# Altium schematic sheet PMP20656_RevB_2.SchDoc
size 431 x 279 mm; Date: Not shown in title block; ApprovedBy: Not shown in title block; CheckedBy: Not shown in title block; Author: Not shown in title block; CompanyName: Not shown in title block; Engineer: Not shown in title block; Organization: Not shown in title block; Address1: Not shown in title block; Address2: Not shown in title block; Address3: Not shown in title block; Address4: Not shown in title block; DocumentNumber: 2; Revision: Use project parameter SCH_Rev; SheetNumber: 2; SheetTotal: 2; PageSetup: Record=PageOptions¦CenterHorizontal=True¦CenterVertical=True¦PrintScale=1.00¦XCorrection=1.00¦YCorrection=1.00¦PrintKind=0¦BorderSize=5000000¦LeftOffset=0¦BottomOffset=0¦Orientation=2¦PaperLength=1000¦PaperWidth=1000¦Scale=100¦PaperSource=15¦PrintQuality=600¦MediaType=1¦DitherType=10¦PaperKind=Letter¦PrintScaleMode=1
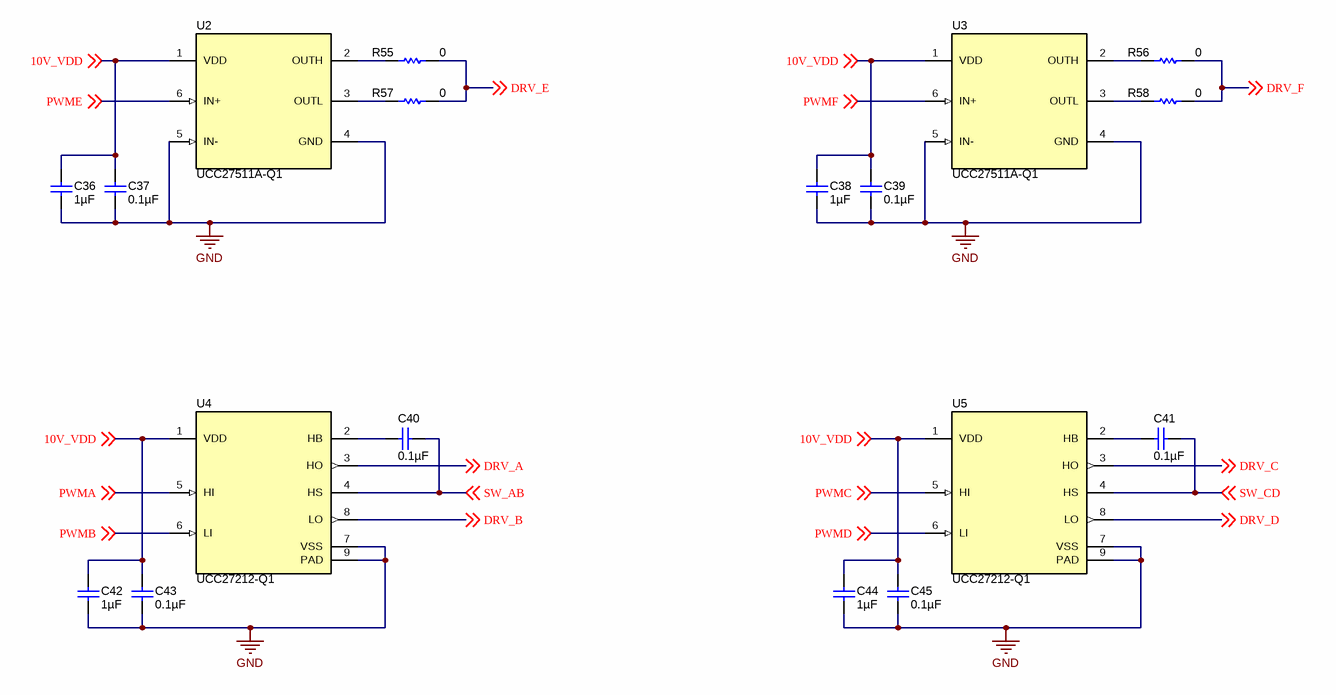
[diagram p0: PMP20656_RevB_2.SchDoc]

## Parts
C36  ValueDisplayed: 1µF  [0603L]  (hidden comment: GRM188R71E105KA12D)
C37  ValueDisplayed: 0.1µF  [0603L]  (hidden comment: GRM188R71H104KA93D)
C38  ValueDisplayed: 1µF  [0603L]  (hidden comment: GRM188R71E105KA12D)
C39  ValueDisplayed: 0.1µF  [0603L]  (hidden comment: GRM188R71H104KA93D)
C40  ValueDisplayed: 0.1µF  [0603L]  (hidden comment: GRM188R71H104KA93D)
C41  ValueDisplayed: 0.1µF  [0603L]  (hidden comment: GRM188R71H104KA93D)
C42  ValueDisplayed: 1µF  [0603L]  (hidden comment: GRM188R71E105KA12D)
C43  ValueDisplayed: 0.1µF  [0603L]  (hidden comment: GRM188R71H104KA93D)
C44  ValueDisplayed: 1µF  [0603L]  (hidden comment: GRM188R71E105KA12D)
C45  ValueDisplayed: 0.1µF  [0603L]  (hidden comment: GRM188R71H104KA93D)
R55  ValueDisplayed: 0  [0603L]  (hidden comment: CRCW06030000Z0EA)
R56  ValueDisplayed: 0  [0603L]  (hidden comment: CRCW06030000Z0EA)
R57  ValueDisplayed: 0  [0603L]  (hidden comment: CRCW06030000Z0EA)
R58  ValueDisplayed: 0  [0603L]  (hidden comment: CRCW06030000Z0EA)
U2  UCC27511A-Q1  [DBV0006A_N]
U3  UCC27511A-Q1  [DBV0006A_N]
U4  UCC27212-Q1  [DDA0008E_N]
U5  UCC27212-Q1  [DDA0008E_N]

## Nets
GND: C36.2 C37.2 C38.2 C39.2 C42.2 C43.2 C44.2 C45.2 U2.4(GND) U2.5(IN-) U3.4(GND) U3.5(IN-) U4.7(VSS) U4.9(PAD) U5.7(VSS) U5.9(PAD)
10V_VDD: C36.1 C37.1 C38.1 C39.1 C42.1 C43.1 C44.1 C45.1 U2.1(VDD) U3.1(VDD) U4.1(VDD) U5.1(VDD) ; off-sheet 10V_VDD
DRV_A: U4.3(HO) ; off-sheet DRV_A
DRV_B: U4.8(LO) ; off-sheet DRV_B
DRV_C: U5.3(HO) ; off-sheet DRV_C
DRV_D: U5.8(LO) ; off-sheet DRV_D
DRV_E: R55.1 R57.1 ; off-sheet DRV_E
DRV_F: R56.1 R58.1 ; off-sheet DRV_F
PWMA: U4.5(HI) ; off-sheet PWMA
PWMB: U4.6(LI) ; off-sheet PWMB
PWMC: U5.5(HI) ; off-sheet PWMC
PWMD: U5.6(LI) ; off-sheet PWMD
PWME: U2.6(IN+) ; off-sheet PWME
PWMF: U3.6(IN+) ; off-sheet PWMF
SW_AB: C40.2 U4.4(HS) ; off-sheet SW_AB
SW_CD: C41.2 U5.4(HS) ; off-sheet SW_CD
NetC40_1: C40.1 U4.2(HB)
NetC41_1: C41.1 U5.2(HB)
NetR55_2: R55.2 U2.2(OUTH)
NetR56_2: R56.2 U3.2(OUTH)
NetR57_2: R57.2 U2.3(OUTL)
NetR58_2: R58.2 U3.3(OUTL)

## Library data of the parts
C36 C38 C42 C44 = GRM188R71E105KA12D: CAP, CERM, 1 µF, 25 V, +/- 10%, X7R, 0603; Manufacturer: MuRata; Polarized: N; CompType: Capacitor; Value: 1uF; U/M: EA; Cap_F: 0.000001; Tolerance_%: 10; Value1: Unknown; VDC_V: 25; Value2: 25V; TaMin_C: -55; TaMax_C: 125; Cap_Case: 0603; SizeArea_mm2: 1.28; SizeAreaWB_mm2: 4.68; SizeX_mm: 1.6; SizeY_mm: 0.8; SizeZ_mm: 1; AEC Category: Q200
C37 C39-C41 C43 C45 = GRM188R71H104KA93D: CAP, CERM, 0.1 µF, 50 V, +/- 10%, X7R, 0603; Manufacturer: MuRata; Polarized: N; CompType: Capacitor; Value: 0.1uF; U/M: EA; Cap_F: 0.0000001; Tolerance_%: 10; Value1: Unknown; VDC_V: 50; Value2: 50V; TaMin_C: -55; TaMax_C: 125; Cap_Case: 0603; SizeArea_mm2: 1.28; SizeAreaWB_mm2: 4.68; SizeX_mm: 1.6; SizeY_mm: 0.8; SizeZ_mm: 1; AEC Category: Q200
R55-R58 = CRCW06030000Z0EA: RES, 0, 5%, 0.1 W, 0603; Manufacturer: Vishay-Dale; CompType: Resistor; Value: 0; Value_Code: 0000; Tolerance_%: 5; Power_W: 0.1; Value2: 0.1W; VDC_V: 75; TempCo: 200 ppm/C; SizeArea_mm2: 1.28; SizeX_mm: 1.6; SizeY_mm: 0.8; SizeZ_mm: 1; EIA_Code: E24; U/M: EA; AEC Category: Q200
U2 U3 = UCC27511DBVR: Single-Channel High-Speed Low-Side Gate Driver (with 4-A Peak Source and 8-A Peak Sink), DBV0006A (SOT-6); PartNumber: UCC27511AQDBVRQ1; Manufacturer: Texas Instruments; SymbolCreator: a0411947; SizeArea_mm2: 8.12; SizeAreaWB_mm2: 14.82; SizeX_mm: 2.8; SizeY_mm: 2.9; SizeZ_mm: 1.45; CompType: IC; U/M: EA
U4 = UCC27211AQDDARQ1: 120-V Boot, 4-A Peak, High Frequency High-Side and Low-Side Driver, DDA0008E (SOIC-8); PartNumber: UCC27212AQDDARQ1; Manufacturer: Texas Instruments; SymbolCreator: a0411947; SizeArea_mm2: 31; SizeAreaWB_mm2: 57.4; SizeX_mm: 5; SizeY_mm: 6.2; SizeZ_mm: 1.7; CompType: IC; U/M: EA
U5 = UCC27211AQDDARQ1: 120-V Boot, 4-A Peak, High Frequency High-Side and Low-Side Driver, DDA0008E (SOIC-8); Manufacturer: Texas Instruments; SymbolCreator: a0411947; SizeArea_mm2: 31; SizeAreaWB_mm2: 57.4; SizeX_mm: 5; SizeY_mm: 6.2; SizeZ_mm: 1.7; CompType: IC; U/M: EA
